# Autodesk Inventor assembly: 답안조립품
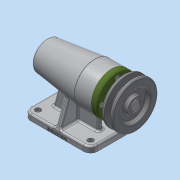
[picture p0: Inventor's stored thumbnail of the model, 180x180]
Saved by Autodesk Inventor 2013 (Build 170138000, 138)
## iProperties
Created: 2018-09
Part Number: 답안조립품
Document SubType Name: Assembly
Designer: dgall
Author: dgall
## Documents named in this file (12)
- C:\Users\dgall\Desktop\480907V1021\답안조립품.iam
- C:\Users\dgall\Desktop\480907V1021\본체.ipt
- C:\Users\dgall\Desktop\480907V1021\베어링 6004.ipt
- C:\Users\dgall\Desktop\480907V1021\베어링 51202.ipt
- C:\Users\dgall\Desktop\480907V1021\볼트 M4.ipt
- C:\Users\dgall\Desktop\480907V1021\어댑터슬리브.ipt
- C:\Users\dgall\Desktop\480907V1021\축.ipt
- C:\Users\dgall\Desktop\480907V1021\키 5 x 5 x 16.ipt
- C:\Users\dgall\Desktop\480907V1021\오일 실.ipt
- C:\Users\dgall\Desktop\480907V1021\커버.ipt
- C:\Users\dgall\Desktop\480907V1021\V벨트풀리.ipt
- C:\Users\dgall\Desktop\480907V1021\멈춤나사 M3.ipt
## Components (1 placed, 1 different names)
1. V벨트풀리:1
